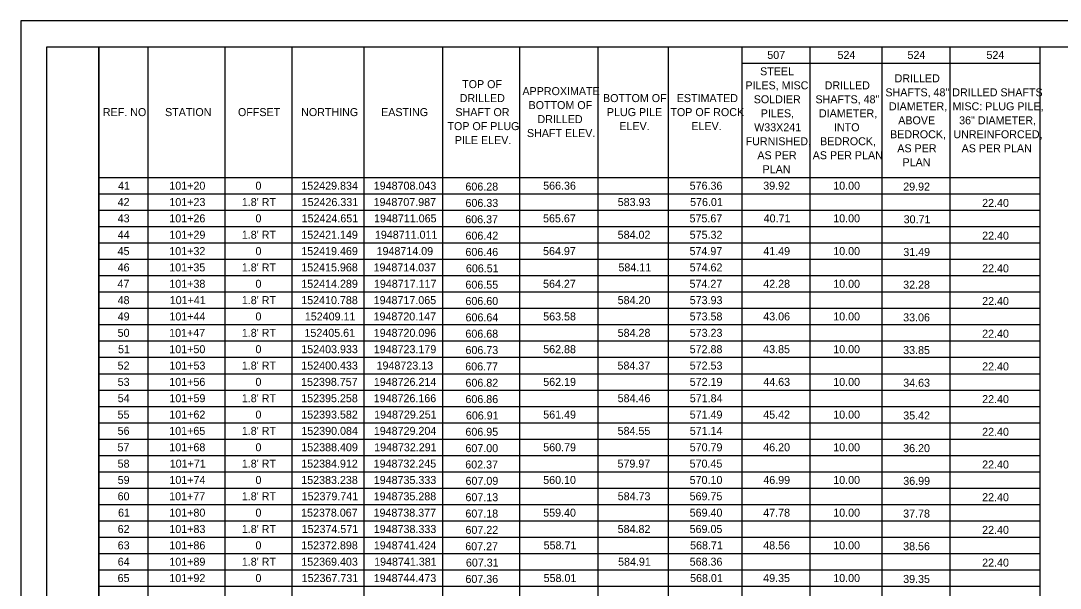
# Model space of a CAD drawing. Extents: x 0 to 34, y 0 to 22.
# Drawn here: x 0 to 20.01, y 11.07 to 22 of the extents above; entities that cross this region are included whole.
import ezdxf

# ---------------------------------------------------------------- set-up
doc = ezdxf.new("R2010")
doc.units = 0
for name, color, linetype in [('Default', 7, 'Continuous'), ('SH_Data', 7, 'Continuous'), ('SH_Text', 7, 'Continuous')]:
    doc.layers.add(name, color=color, linetype=linetype)

msp = doc.modelspace()

# ---------------------------------------------------------------- linework, layer by layer
at = {"layer": 'Default'}
for p, q in [((1.5, 21.5), (19.613, 21.5)), ((1.5, 21.5), (1.5, 1.34)), ((2.445, 21.5), (2.445, 1.655)), ((3.926, 21.5), (3.926, 1.655)), ((5.217, 21.5), (5.217, 1.655)), ((6.603, 21.5), (6.603, 1.655)), ((8.115, 21.5), (8.115, 1.655)), ((9.596, 21.5), (9.596, 1.655)), ((11.108, 21.5), (11.108, 1.655)), ((12.462, 21.5), (12.462, 1.655)), ((13.88, 21.5), (13.88, 1.34)), ((15.187, 21.5), (15.187, 1.34)), ((16.573, 21.5), (16.573, 1.34)), ((17.88, 21.5), (17.88, 1.34)), ((19.613, 21.5), (19.613, 1.34)), ((13.88, 21.185), (19.613, 21.185)), ((1.5, 18.98), (19.613, 18.98)), ((1.5, 18.665), (19.613, 18.665)), ((1.5, 18.35), (19.613, 18.35)), ((1.5, 18.035), (19.613, 18.035)), ((1.5, 17.72), (19.613, 17.72)), ((1.5, 17.405), (19.613, 17.405)), ((1.5, 17.09), (19.613, 17.09)), ((1.5, 16.775), (19.613, 16.775)), ((1.5, 16.46), (19.613, 16.46)), ((1.5, 16.145), (19.613, 16.145)), ((1.5, 15.83), (19.613, 15.83)), ((1.5, 15.515), (19.613, 15.515)), ((1.5, 15.2), (19.613, 15.2)), ((1.5, 14.885), (19.613, 14.885)), ((1.5, 14.57), (19.613, 14.57)), ((1.5, 14.255), (19.613, 14.255)), ((1.5, 13.94), (19.613, 13.94)), ((1.5, 13.625), (19.613, 13.625)), ((1.5, 13.31), (19.613, 13.31)), ((1.5, 12.995), (19.613, 12.995)), ((1.5, 12.68), (19.613, 12.68)), ((1.5, 12.365), (19.613, 12.365)), ((1.5, 12.05), (19.613, 12.05)), ((1.5, 11.735), (19.613, 11.735)), ((1.5, 11.42), (19.613, 11.42)), ((1.5, 11.105), (19.613, 11.105))]:
    msp.add_line(p, q, dxfattribs=at)
at = {"layer": 'SH_Data'}
for points in [[(0.5, 21.5), (1.5, 21.5), (1.5, 0.5), (0.5, 0.5)], [(1.5, 21.5), (33.5, 21.5), (33.5, 0.5), (1.5, 0.5)]]:
    msp.add_lwpolyline(points, close=True, dxfattribs=at)
at = {"layer": 'SH_Text'}
msp.add_lwpolyline([(0, 0), (34, 0), (34, 22), (0, 22)], close=True, dxfattribs=at)

# ---------------------------------------------------------------- texts
at = {"layer": 'Default'}
for s, p in [('507', (14.368, 21.265)), ('524', (15.719, 21.265)), ('524', (17.066, 21.265)), ('524', (18.586, 21.265)), ('STEEL ', (14.229, 20.949)), ('TOP OF ', (8.495, 20.702)), ('PILES, MISC. ', (13.946, 20.679)), ('DRILLED ', (15.472, 20.679)), ('DRILLED ', (16.818, 20.814)), ('APPROXIMATE ', (9.655, 20.567)), ('SHAFTS, 48" ', (16.641, 20.544)), ('DRILLED SHAFTS ', (17.928, 20.544)), ('DRILLED ', (8.447, 20.433)), ('BOTTOM OF ', (9.773, 20.298)), ('BOTTOM OF ', (11.206, 20.433)), ('ESTIMATED ', (12.625, 20.433)), ('SOLDIER ', (14.107, 20.41)), ('SHAFTS, 48" ', (15.295, 20.41)), ('DIAMETER, ', (16.709, 20.275)), ('MISC: PLUG PILE, ', (17.933, 20.275)), ('REF. NO', (1.58, 20.163)), ('STATION', (2.777, 20.163)), ('OFFSET', (4.18, 20.163)), ('NORTHING', (5.396, 20.163)), ('EASTING', (6.935, 20.163)), ('SHAFT OR ', (8.365, 20.163)), ('PLUG PILE ', (11.28, 20.163)), ('TOP OF ROCK ', (12.503, 20.163)), ('PILES, ', (14.242, 20.14)), ('DIAMETER, ', (15.362, 20.14)), ('TOP OF PLUG ', (8.212, 19.893)), ('DRILLED ', (9.944, 20.028)), ('ELEV.', (11.52, 19.893)), ('ELEV.', (12.906, 19.893)), ('W33X241 ', (14.115, 19.871)), ('INTO ', (15.651, 19.871)), ('ABOVE ', (16.888, 20.005)), ('36" DIAMETER, ', (18.06, 20.005)), ('SHAFT ELEV.', (9.742, 19.759)), ('BEDROCK, ', (16.731, 19.736)), ('UNREINFORCED, ', (17.949, 19.736)), ('PILE ELEV.', (8.354, 19.624)), ('FURNISHED, ', (13.951, 19.601)), ('BEDROCK, ', (15.384, 19.601)), ('AS PER ', (16.87, 19.466)), ('AS PER PLAN', (18.108, 19.466)), ('AS PER ', (14.177, 19.332)), ('AS PER PLAN', (15.242, 19.332)), ('PLAN', (14.277, 19.062)), ('PLAN', (16.97, 19.197)), ('41', (1.872, 18.745)), ('101+20', (2.859, 18.745)), ('0', (4.517, 18.745)), ('152429.834', (5.4, 18.745)), ('1948708.043', (6.794, 18.745)), ('606.28', (8.558, 18.728)), ('566.36', (10.054, 18.745)), ('576.36', (12.874, 18.745)), ('39.92', (14.29, 18.745)), ('10.00', (15.637, 18.745)), ('29.92', (16.984, 18.728)), ('42', (1.864, 18.43)), ('101+23', (2.86, 18.43)), ("1.8' RT", (4.254, 18.43)), ('152426.331', (5.406, 18.43)), ('1948707.987', (6.79, 18.43)), ('606.33', (8.559, 18.413)), ('583.93', (11.489, 18.43)), ('576.01', (12.882, 18.43)), ('22.40', (18.503, 18.413)), ('43', (1.865, 18.116)), ('101+26', (2.859, 18.116)), ('0', (4.517, 18.116)), ('152424.651', (5.406, 18.116)), ('1948711.065', (6.799, 18.116)), ('606.37', (8.555, 18.098)), ('565.67', (10.052, 18.116)), ('575.67', (12.871, 18.116)), ('40.71', (14.298, 18.116)), ('10.00', (15.637, 18.116)), ('30.71', (16.992, 18.098)), ('44', (1.866, 17.8)), ('101+29', (2.86, 17.8)), ("1.8' RT", (4.254, 17.8)), ('152421.149', (5.399, 17.8)), ('1948711.011', (6.816, 17.8)), ('606.42', (8.559, 17.783)), ('584.02', (11.488, 17.8)), ('575.32', (12.874, 17.8)), ('22.40', (18.503, 17.783)), ('45', (1.863, 17.485)), ('101+32', (2.859, 17.485)), ('0', (4.517, 17.485)), ('152419.469', (5.399, 17.485)), ('1948714.09', (6.848, 17.485)), ('606.46', (8.558, 17.468)), ('564.97', (10.052, 17.485)), ('574.97', (12.871, 17.485)), ('41.49', (14.291, 17.485)), ('10.00', (15.637, 17.485)), ('31.49', (16.985, 17.468)), ('46', (1.864, 17.171)), ('101+35', (2.858, 17.171)), ("1.8' RT", (4.254, 17.171)), ('152415.968', (5.398, 17.171)), ('1948714.037', (6.79, 17.171)), ('606.51', (8.567, 17.153)), ('584.11', (11.503, 17.171)), ('574.62', (12.874, 17.171)), ('22.40', (18.503, 17.153)), ('47', (1.861, 16.855)), ('101+38', (2.859, 16.855)), ('0', (4.517, 16.855)), ('152414.289', (5.399, 16.855)), ('1948717.117', (6.797, 16.855)), ('564.27', (10.052, 16.855)), ('574.27', (12.871, 16.855)), ('42.28', (14.29, 16.855)), ('10.00', (15.637, 16.855)), ('606.55', (8.558, 16.838)), ('32.28', (16.983, 16.838)), ('48', (1.864, 16.54)), ('101+41', (2.867, 16.54)), ("1.8' RT", (4.254, 16.54)), ('152410.788', (5.398, 16.54)), ('1948717.065', (6.792, 16.54)), ('606.60', (8.558, 16.523)), ('584.20', (11.488, 16.54)), ('573.93', (12.875, 16.54)), ('22.40', (18.503, 16.523)), ('49', (1.865, 16.226)), ('101+44', (2.861, 16.226)), ('0', (4.517, 16.226)), ('152409.11', (5.467, 16.226)), ('1948720.147', (6.79, 16.226)), ('606.64', (8.56, 16.208)), ('563.58', (10.055, 16.226)), ('573.58', (12.874, 16.226)), ('43.06', (14.29, 16.226)), ('10.00', (15.637, 16.226)), ('33.06', (16.983, 16.208)), ('50', (1.864, 15.91)), ('101+47', (2.856, 15.91)), ("1.8' RT", (4.254, 15.91)), ('152405.61', (5.46, 15.91)), ('1948720.096', (6.793, 15.91)), ('606.68', (8.558, 15.893)), ('584.28', (11.488, 15.91)), ('573.23', (12.875, 15.91)), ('22.40', (18.503, 15.893)), ('51', (1.872, 15.595)), ('101+50', (2.859, 15.595)), ('0', (4.517, 15.595)), ('152403.933', (5.399, 15.595)), ('1948723.179', (6.794, 15.595)), ('606.73', (8.559, 15.578)), ('562.88', (10.055, 15.595)), ('572.88', (12.874, 15.595)), ('43.85', (14.289, 15.595)), ('10.00', (15.637, 15.595)), ('33.85', (16.983, 15.578)), ('52', (1.864, 15.28)), ('101+53', (2.86, 15.28)), ("1.8' RT", (4.254, 15.28)), ('152400.433', (5.399, 15.28)), ('1948723.13', (6.848, 15.28)), ('606.77', (8.555, 15.263)), ('584.37', (11.485, 15.28)), ('572.53', (12.875, 15.28)), ('22.40', (18.503, 15.263)), ('53', (1.865, 14.965)), ('101+56', (2.859, 14.965)), ('0', (4.517, 14.965)), ('152398.757', (5.395, 14.965)), ('1948726.214', (6.795, 14.965)), ('606.82', (8.559, 14.948)), ('562.19', (10.056, 14.965)), ('572.19', (12.875, 14.965)), ('44.63', (14.291, 14.965)), ('10.00', (15.637, 14.965)), ('34.63', (16.984, 14.948)), ('54', (1.866, 14.65)), ('101+59', (2.86, 14.65)), ("1.8' RT", (4.254, 14.65)), ('152395.258', (5.398, 14.65)), ('1948726.166', (6.793, 14.65)), ('584.46', (11.488, 14.65)), ('571.84', (12.876, 14.65)), ('606.86', (8.558, 14.633)), ('22.40', (18.503, 14.633)), ('55', (1.863, 14.335)), ('101+62', (2.859, 14.335)), ('0', (4.517, 14.335)), ('152393.582', (5.398, 14.335)), ('1948729.251', (6.801, 14.335)), ('606.91', (8.567, 14.318)), ('561.49', (10.056, 14.335)), ('571.49', (12.875, 14.335)), ('45.42', (14.29, 14.335)), ('10.00', (15.637, 14.335)), ('35.42', (16.984, 14.318)), ('56', (1.864, 14.021)), ('101+65', (2.858, 14.021)), ("1.8' RT", (4.254, 14.021)), ('152390.084', (5.4, 14.021)), ('1948729.204', (6.795, 14.021)), ('606.95', (8.558, 14.003)), ('584.55', (11.487, 14.021)), ('571.14', (12.876, 14.021)), ('22.40', (18.503, 14.003)), ('57', (1.861, 13.705)), ('101+68', (2.859, 13.705)), ('0', (4.517, 13.705)), ('152388.409', (5.399, 13.705)), ('1948732.291', (6.801, 13.705)), ('607.00', (8.558, 13.688)), ('560.79', (10.056, 13.705)), ('570.79', (12.875, 13.705)), ('46.20', (14.29, 13.705)), ('10.00', (15.637, 13.705)), ('36.20', (16.983, 13.688)), ('58', (1.864, 13.39)), ('101+71', (2.867, 13.39)), ("1.8' RT", (4.254, 13.39)), ('152384.912', (5.398, 13.39)), ('1948732.245', (6.792, 13.39)), ('602.37', (8.555, 13.373)), ('579.97', (11.485, 13.39)), ('570.45', (12.873, 13.39)), ('22.40', (18.503, 13.373)), ('59', (1.865, 13.075)), ('101+74', (2.861, 13.075)), ('0', (4.517, 13.075)), ('152383.238', (5.398, 13.075)), ('1948735.333', (6.794, 13.075)), ('607.09', (8.56, 13.058)), ('560.10', (10.055, 13.075)), ('570.10', (12.874, 13.075)), ('46.99', (14.291, 13.075)), ('10.00', (15.637, 13.075)), ('36.99', (16.985, 13.058)), ('60', (1.864, 12.761)), ('101+77', (2.856, 12.761)), ("1.8' RT", (4.254, 12.761)), ('152379.741', (5.406, 12.761)), ('1948735.288', (6.793, 12.761)), ('607.13', (8.559, 12.743)), ('584.73', (11.489, 12.761)), ('569.75', (12.873, 12.761)), ('22.40', (18.503, 12.743)), ('61', (1.872, 12.445)), ('101+80', (2.859, 12.445)), ('0', (4.517, 12.445)), ('152378.067', (5.395, 12.445)), ('1948738.377', (6.79, 12.445)), ('607.18', (8.558, 12.428)), ('559.40', (10.055, 12.445)), ('569.40', (12.874, 12.445)), ('47.78', (14.29, 12.445)), ('10.00', (15.637, 12.445)), ('37.78', (16.983, 12.428)), ('62', (1.864, 12.13)), ('101+83', (2.86, 12.13)), ("1.8' RT", (4.254, 12.13)), ('152374.571', (5.406, 12.13)), ('1948738.333', (6.794, 12.13)), ('607.22', (8.559, 12.113)), ('584.82', (11.488, 12.13)), ('569.05', (12.873, 12.13)), ('22.40', (18.503, 12.113)), ('63', (1.865, 11.816)), ('101+86', (2.859, 11.816)), ('0', (4.517, 11.816)), ('152372.898', (5.398, 11.816)), ('1948741.424', (6.795, 11.816)), ('607.27', (8.555, 11.798)), ('558.71', (10.063, 11.816)), ('568.71', (12.882, 11.816)), ('48.56', (14.29, 11.816)), ('10.00', (15.637, 11.816)), ('38.56', (16.983, 11.798)), ('64', (1.866, 11.5)), ('101+89', (2.86, 11.5)), ("1.8' RT", (4.254, 11.5)), ('152369.403', (5.399, 11.5)), ('1948741.381', (6.801, 11.5)), ('607.31', (8.567, 11.483)), ('584.91', (11.496, 11.5)), ('568.36', (12.874, 11.5)), ('22.40', (18.503, 11.483)), ('65', (1.863, 11.185)), ('101+92', (2.859, 11.185)), ('0', (4.517, 11.185)), ('152367.731', (5.406, 11.185)), ('1948744.473', (6.794, 11.185)), ('607.36', (8.558, 11.168)), ('558.01', (10.063, 11.185)), ('568.01', (12.882, 11.185)), ('49.35', (14.289, 11.185)), ('10.00', (15.637, 11.185)), ('39.35', (16.983, 11.168))]:
    msp.add_text(s, height=0.154, dxfattribs=at).set_placement(p)

doc.saveas('drawing.dxf')
